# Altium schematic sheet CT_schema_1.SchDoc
size 547 x 488 mm
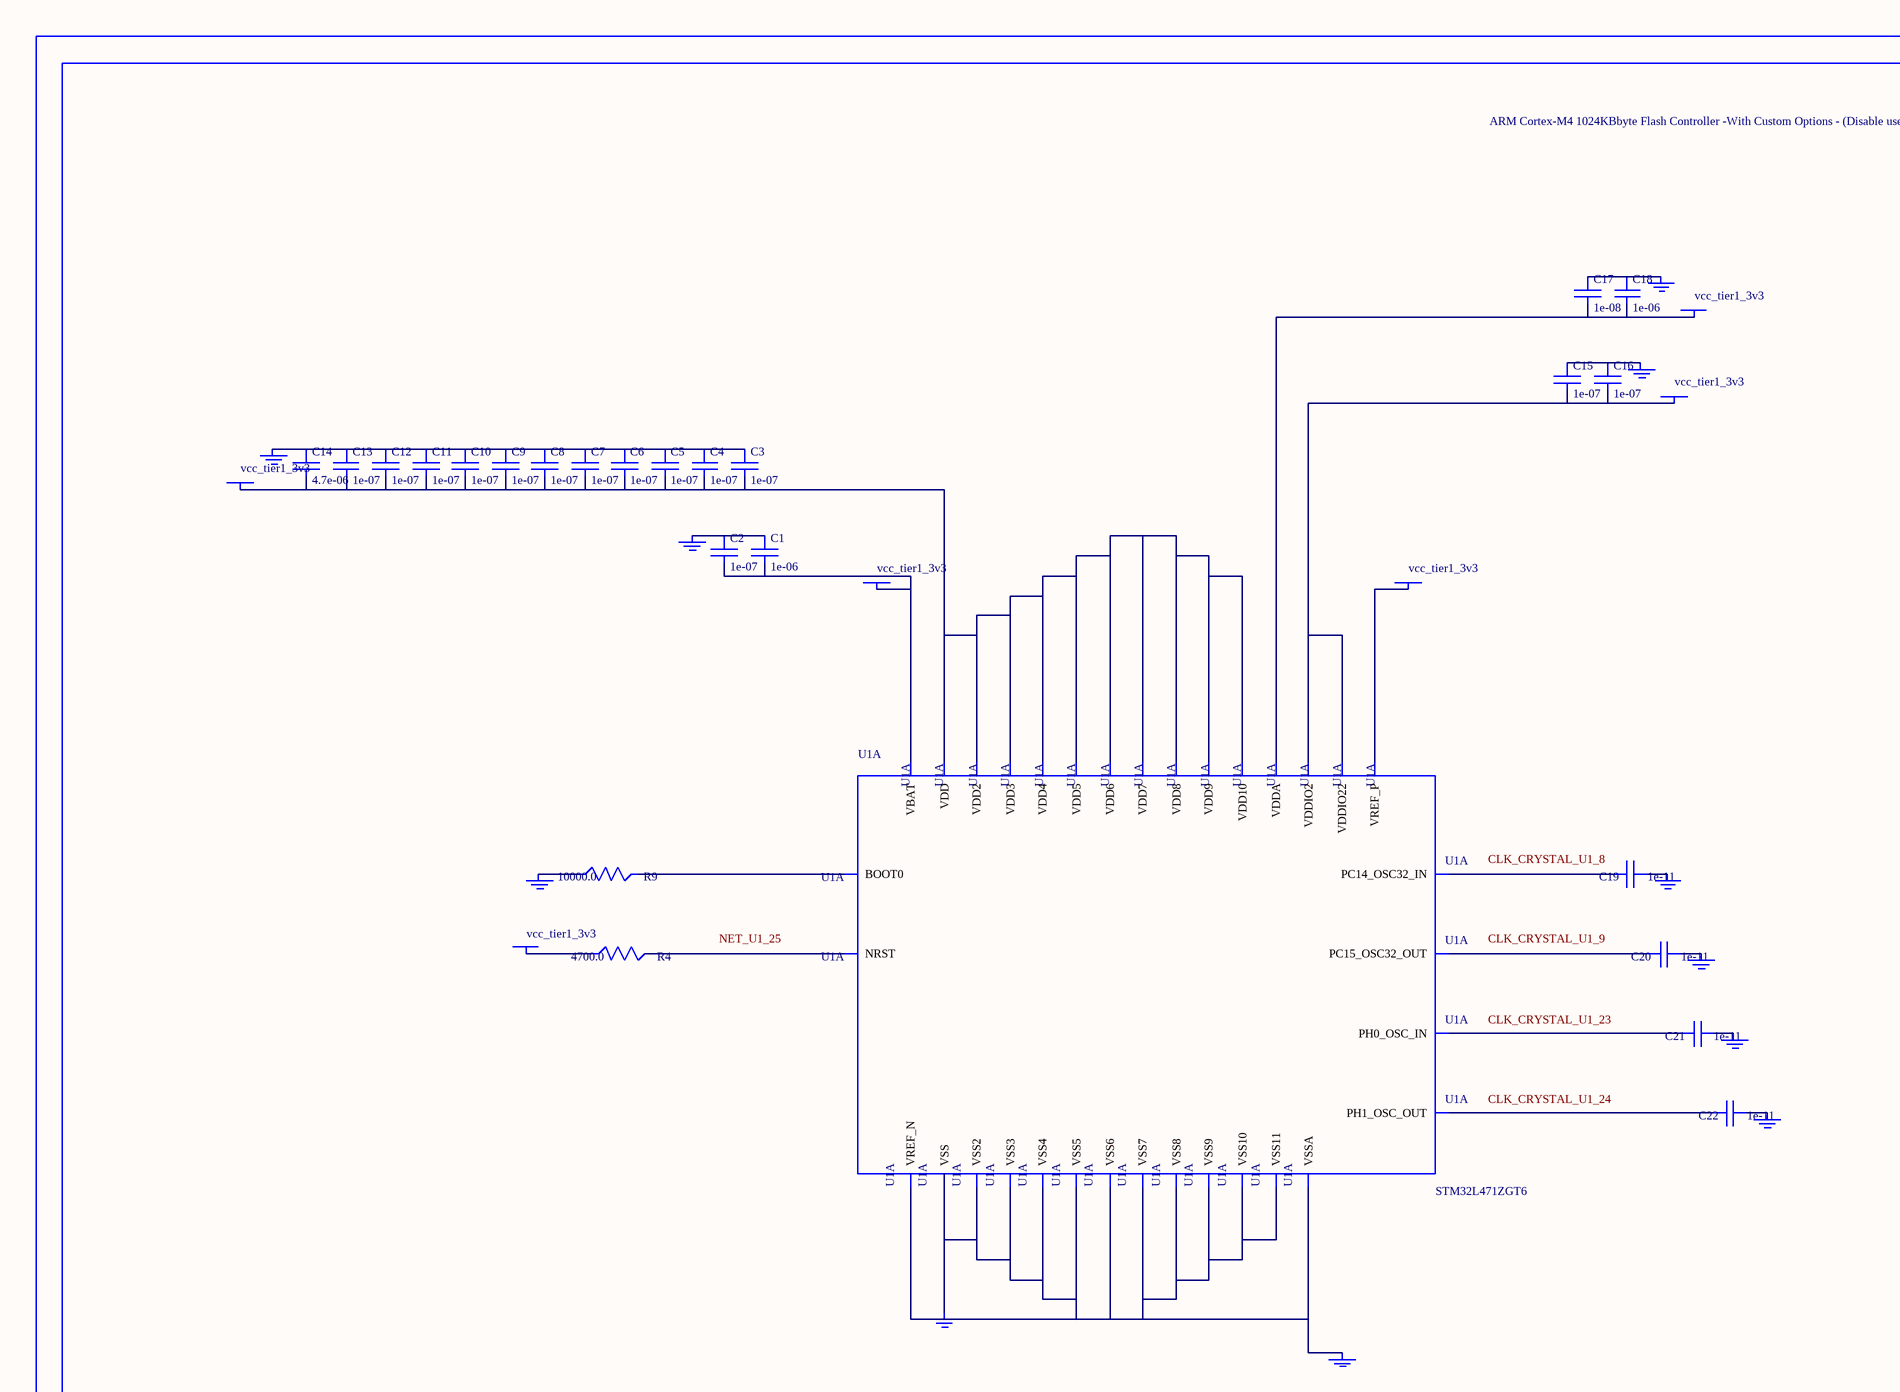
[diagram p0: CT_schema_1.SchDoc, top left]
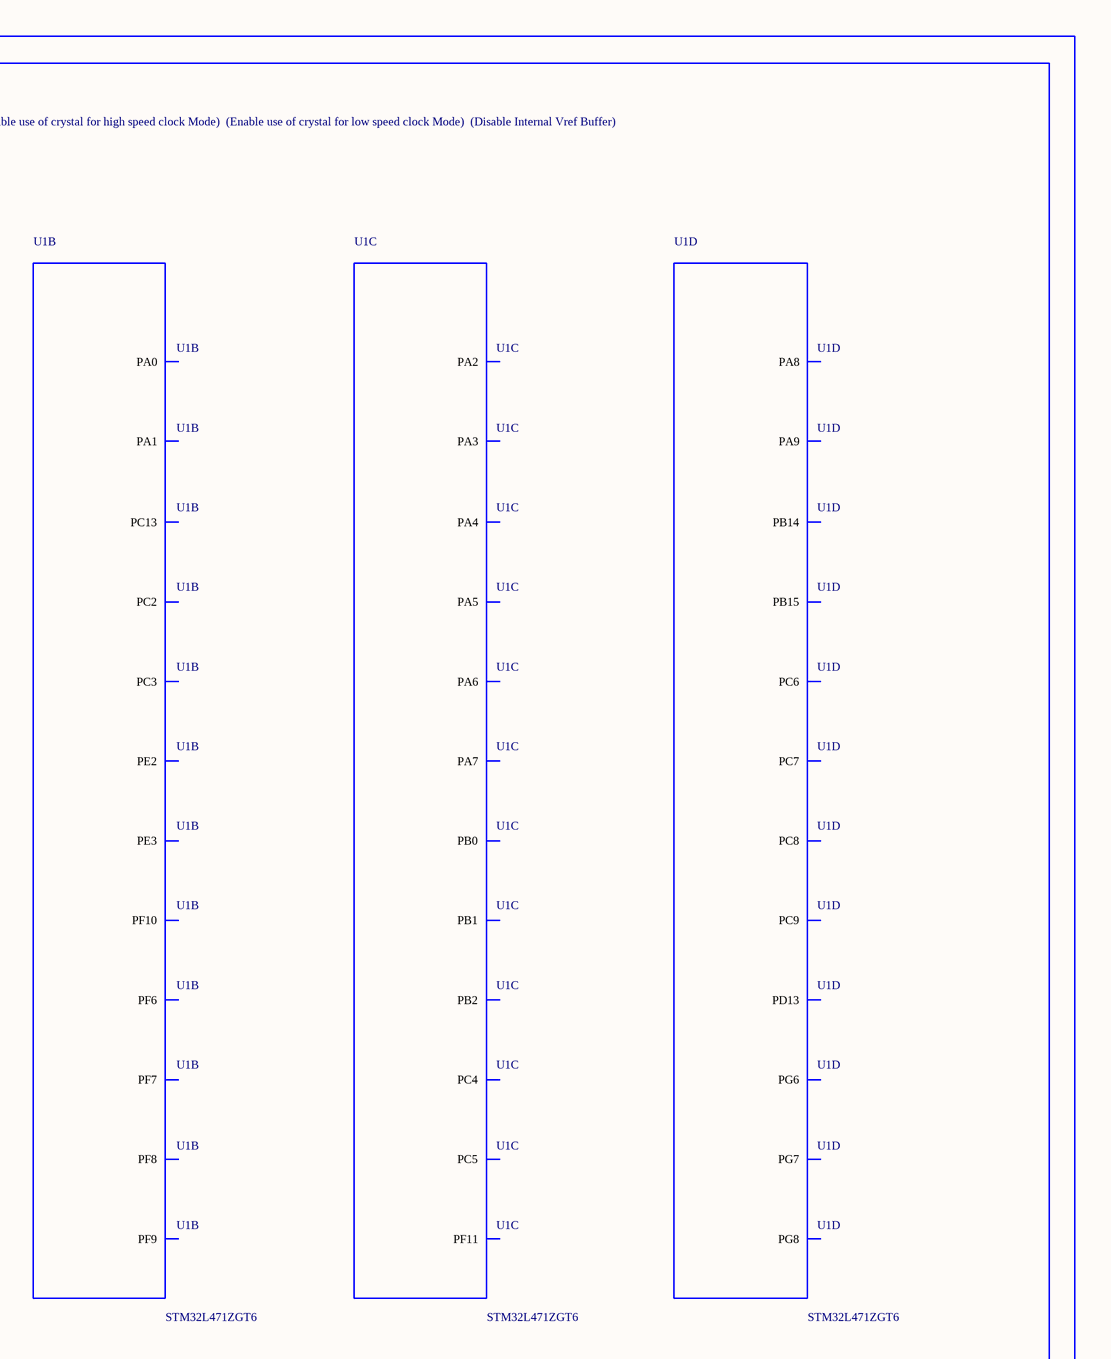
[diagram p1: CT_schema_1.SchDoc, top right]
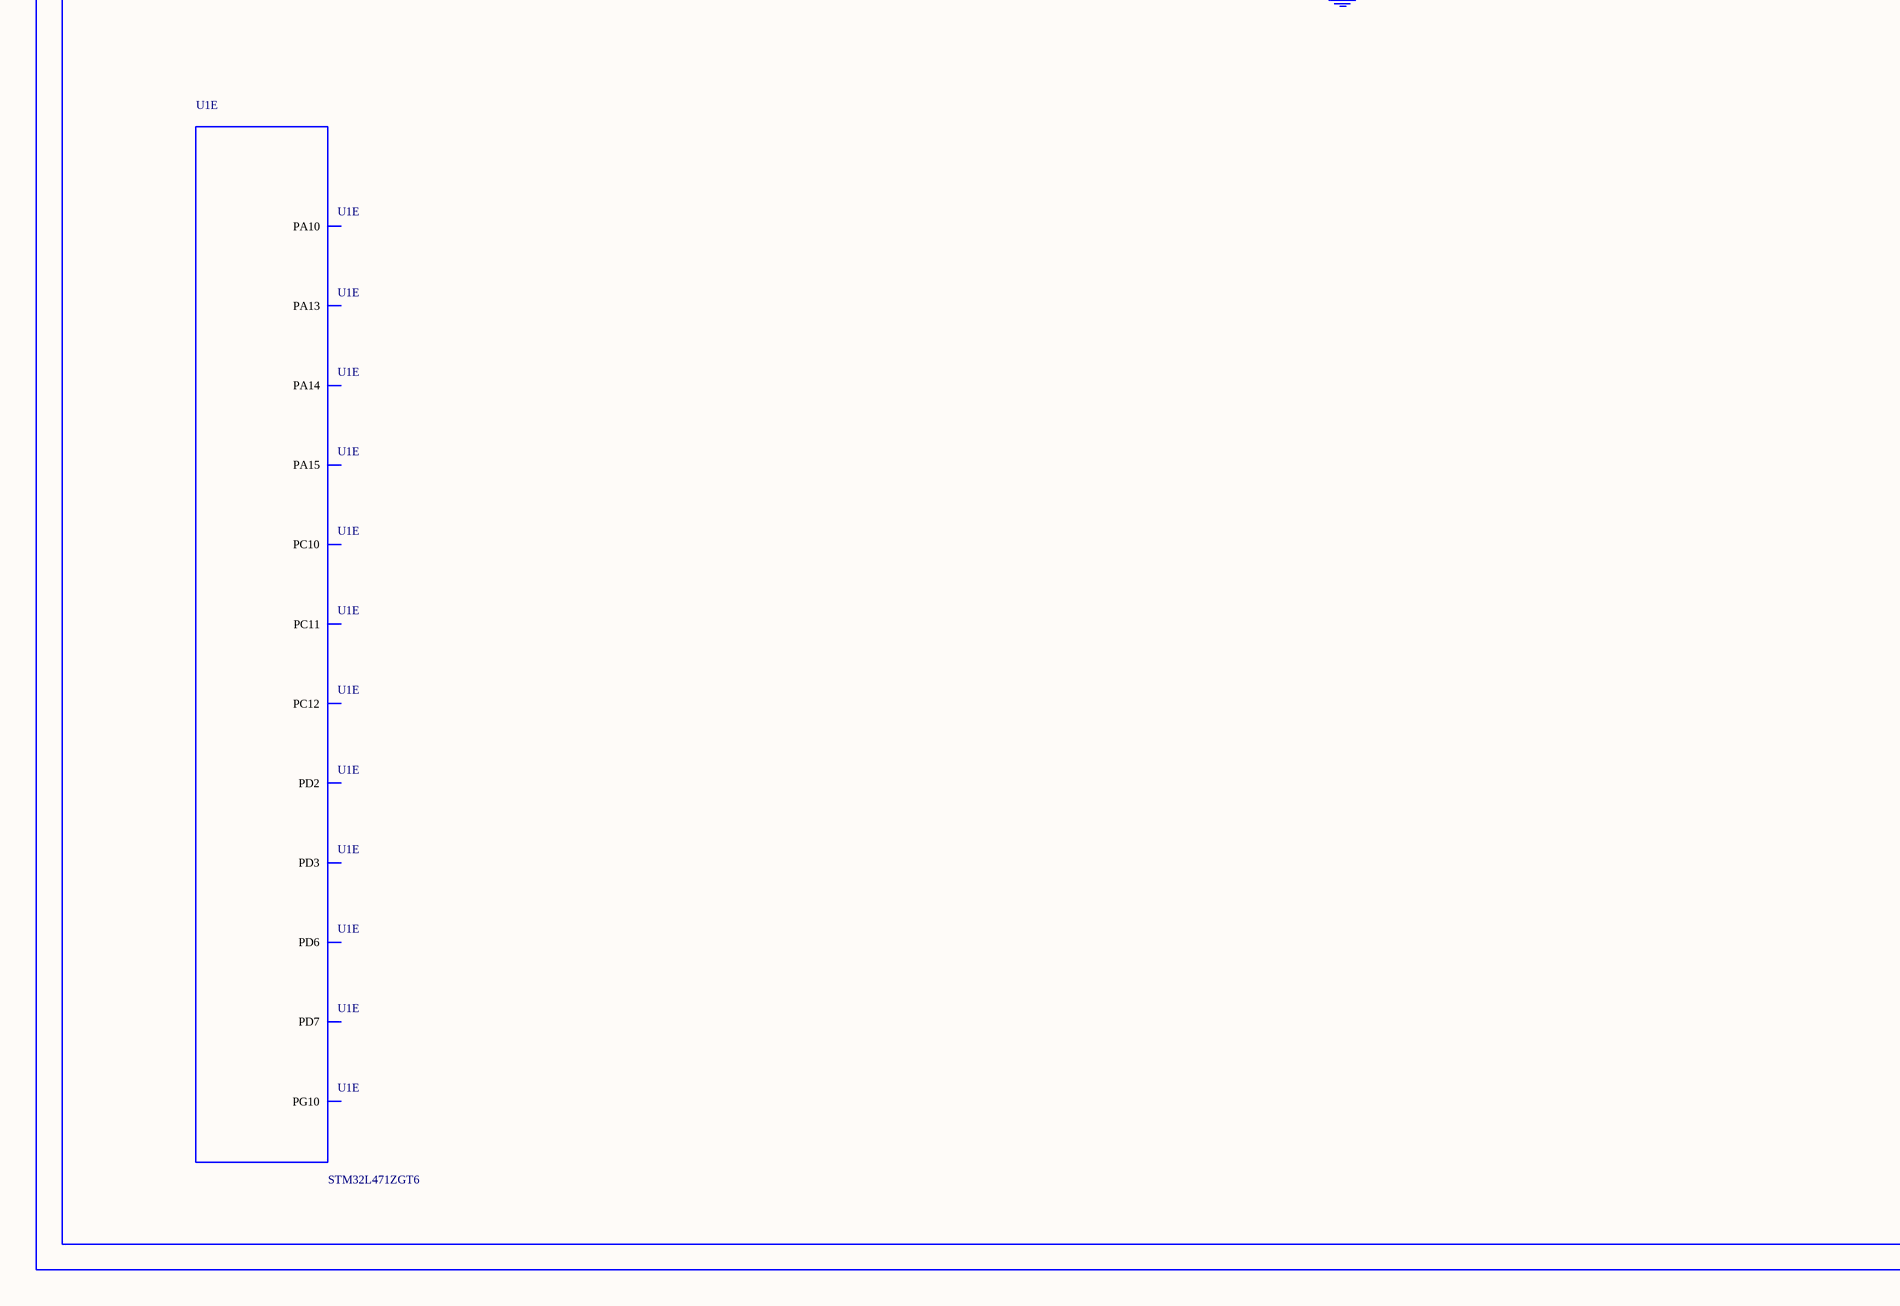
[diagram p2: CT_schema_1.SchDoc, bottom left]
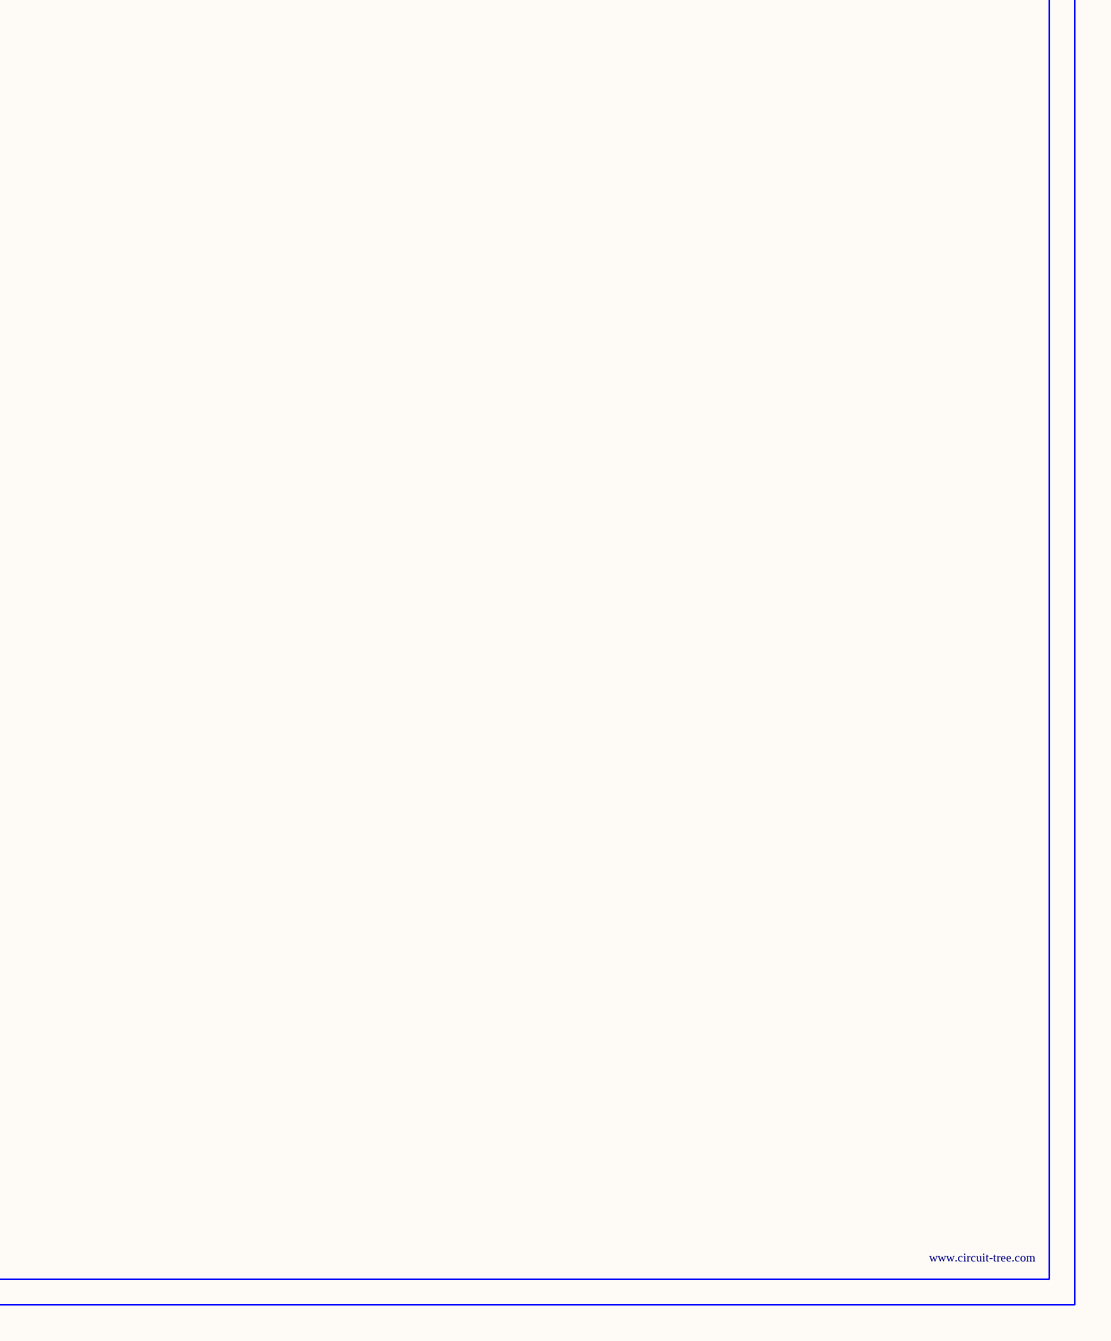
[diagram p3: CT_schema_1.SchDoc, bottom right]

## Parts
BORDER0  (no value)
C1  1e-06  [C0603]
C2  1e-07  [C0603]
C3  1e-07  [C0603]
C4  1e-07  [C0603]
C5  1e-07  [C0603]
C6  1e-07  [C0603]
C7  1e-07  [C0603]
C8  1e-07  [C0603]
C9  1e-07  [C0603]
C10  1e-07  [C0603]
C11  1e-07  [C0603]
C12  1e-07  [C0603]
C13  1e-07  [C0603]
C14  4.7e-06  [C0603]
C15  1e-07  [C0603]
C16  1e-07  [C0603]
C17  1e-08  [C0603]
C18  1e-06  [C0603]
C19  1e-11  [C0402]
C20  1e-11  [C0402]
C21  1e-11  [C0402]
C22  1e-11  [C0402]
GND_INSTANCE_0_0  (no value)
GND_INSTANCE_0_1  (no value)
GND_INSTANCE_0_2  (no value)
GND_INSTANCE_0_3  (no value)
GND_INSTANCE_0_4  (no value)
GND_INSTANCE_0_5  (no value)
GND_INSTANCE_0_6  (no value)
GND_INSTANCE_0_7  (no value)
GND_INSTANCE_0_8  (no value)
GND_INSTANCE_0_9  (no value)
GND_INSTANCE_0_10  (no value)
POWER_INSTANCE_0_0  vcc_tier1_3v3
POWER_INSTANCE_0_1  vcc_tier1_3v3
POWER_INSTANCE_0_2  vcc_tier1_3v3
POWER_INSTANCE_0_3  vcc_tier1_3v3
POWER_INSTANCE_0_4  vcc_tier1_3v3
POWER_INSTANCE_0_5  vcc_tier1_3v3
R4  4700.0  [R0603]
R9  10000.0  [R0603]
U1  STM32L471ZGT6  [LQFP144]  (parts A,B,C,D,E of 14)

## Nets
NetC1_1: C1.1 C2.1 GND_INSTANCE_0_0.0(GND)
NetC1_2: C1.2 C2.2 POWER_INSTANCE_0_0.0(PWR) U1.6(VBAT)
NetC3_1: C3.1 C4.1 C5.1 C6.1 C7.1 C8.1 C9.1 C10.1 C11.1 C12.1 C13.1 C14.1 GND_INSTANCE_0_3.0(GND)
NetC3_2: C3.2 C4.2 C5.2 C6.2 C7.2 C8.2 C9.2 C10.2 C11.2 C12.2 C13.2 C14.2 POWER_INSTANCE_0_1.0(PWR) U1.17(VDD) U1.39(VDD2) U1.52(VDD3) U1.62(VDD4) U1.72(VDD5) U1.84(VDD6) U1.106(VDD7) U1.108(VDD8) U1.121(VDD9) U1.144(VDD10)
NetC15_1: C15.1 C16.1 GND_INSTANCE_0_8.0(GND)
NetC15_2: C15.2 C16.2 POWER_INSTANCE_0_4.0(PWR) U1.95(VDDIO2) U1.131(VDDIO22)
NetC17_1: C17.1 C18.1 GND_INSTANCE_0_7.0(GND)
NetC17_2: C17.2 C18.2 POWER_INSTANCE_0_3.0(PWR) U1.33(VDDA)
NetC19_1: C19.1 GND_INSTANCE_0_1.0(GND)
NetC19_2: C19.2 U1.8(PC14_OSC32_IN)
NetC20_1: C20.1 GND_INSTANCE_0_2.0(GND)
NetC20_2: C20.2 U1.9(PC15_OSC32_OUT)
NetC21_1: C21.1 GND_INSTANCE_0_4.0(GND)
NetC21_2: C21.2 U1.23(PH0_OSC_IN)
NetC22_1: C22.1 GND_INSTANCE_0_5.0(GND)
NetC22_2: C22.2 U1.24(PH1_OSC_OUT)
NetGND_INSTANCE_0_6_0: GND_INSTANCE_0_6.0(GND) GND_INSTANCE_0_10.0(GND) U1.16(VSS) U1.30(VSSA) U1.31(VREF_N) U1.38(VSS2) U1.51(VSS3) U1.61(VSS4) U1.71(VSS5) U1.83(VSS6) U1.94(VSS7) U1.107(VSS8) U1.120(VSS9) U1.130(VSS10) U1.143(VSS11)
NetGND_INSTANCE_0_9_0: GND_INSTANCE_0_9.0(GND) R9.1
NetPOWER_INSTANCE_0_2_0: POWER_INSTANCE_0_2.0(PWR) U1.32(VREF_P)
NetPOWER_INSTANCE_0_5_0: POWER_INSTANCE_0_5.0(PWR) R4.1
NetR4_2: R4.2 U1.25(NRST)
NetR9_2: R9.2 U1.138(BOOT0)

Not connected (* = marked no-connect by the designer): U1 1(PE2) 2(PE3) 7(PC13) 18(PF6) 19(PF7) 20(PF8) 21(PF9) 22(PF10) 28(PC2) 29(PC3) 34(PA0) 35(PA1) 36(PA2) 37(PA3) 40(PA4) 41(PA5) 42(PA6) 43(PA7) 44(PC4) 45(PC5) 46(PB0) 47(PB1) 48(PB2) 49(PF11) 75(PB14) 76(PB15) 82(PD13) 91(PG6) 92(PG7) 93(PG8) 96(PC6) 97(PC7) 98(PC8) 99(PC9) 100(PA8) 101(PA9) 102(PA10) 105(PA13) 109(PA14) 110(PA15) 111(PC10) 112(PC11) 113(PC12) 116(PD2) 117(PD3) 122(PD6) 123(PD7) 125(PG10)

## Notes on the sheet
- Labels drawn without touching a wire or pin: CLK_CRYSTAL_U1_8, CLK_CRYSTAL_U1_9, CLK_CRYSTAL_U1_23, CLK_CRYSTAL_U1_24, NET_U1_25

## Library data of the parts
BORDER0 = BORDER_PAGE0
C1 C18 = C0603C105K3RACTU
C2-C13 C15 C16 = 06035C104K4Z2A
C14 = GRM188R6YA475KE15D
C17 = 06035C103K4Z2A
C19-C22 = C0402C100K3GACTU
GND_INSTANCE_0_0-GND_INSTANCE_0_10 = GND
POWER_INSTANCE_0_0-POWER_INSTANCE_0_5 = PWR
R4 = RC0603JR-074K7L
R9 = RC0603JR-0710KL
